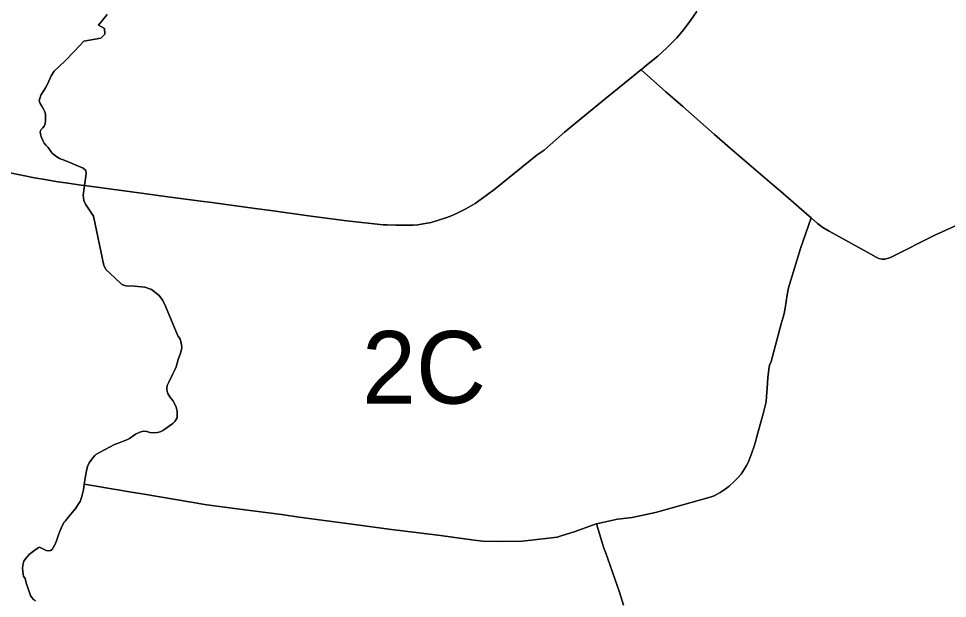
# Model space of a CAD drawing. Extents: x 152750 to 166250, y 378996 to 390000.
# Drawn here: x 161080 to 163640, y 380593 to 382190 of the extents above; entities that cross this region are included whole.
import ezdxf

# ---------------------------------------------------------------- set-up
doc = ezdxf.new("R2010")
doc.units = 0
doc.layers.add('BLT_Nummers', color=7, linetype='Continuous')
doc.layers.add('BLT_Shapes', color=7, linetype='Continuous')

msp = doc.modelspace()

# ---------------------------------------------------------------- linework, layer by layer
at = {"layer": 'BLT_Shapes'}
for p, q in [((162948.6, 382208.9), (162932.1, 382185.3)), ((161317.7, 382147.2), (161316.6, 382163.2)), ((162867.7, 382110.5), (162842, 382086.8)), ((161169.4, 382032.3), (161178.2, 382046)), ((162795.6, 382049.3), (162769.4, 382028.2)), ((162795.9, 382049.5), (162795.6, 382049.3)), ((162821.5, 382026.5), (162795.9, 382049.5)), ((162769.4, 382028.2), (162696.8, 381969.3)), ((162696.8, 381969.3), (162584.7, 381877.3)), ((162998.3, 381870.8), (162910.7, 381948.5)), ((161153, 381900.9), (161154.5, 381909.8)), ((161154.5, 381909.8), (161154.5, 381919.9)), ((161139.7, 381879.4), (161142.1, 381884.7)), ((161155.4, 381842.1), (161150.7, 381847.4)), ((162528.9, 381827.9), (162509.1, 381815.5)), ((161192.6, 381804.9), (161182.6, 381811.1)), ((161210.3, 381798.1), (161192.6, 381804.9)), ((162509.1, 381815.5), (162466.2, 381780.3)), ((162466.2, 381780.3), (162393.5, 381721.5)), ((161261.7, 381730.7), (161265.3, 381756.4)), ((161215.2, 381736.9), (161183, 381741.6)), ((161252.7, 381731.9), (161215.2, 381736.9)), ((161261.7, 381730.7), (161252.7, 381731.9)), ((161261.7, 381730.7), (161258, 381703.8)), ((161258, 381703.8), (161261.7, 381730.7)), ((161259.5, 381689.6), (161258, 381703.8)), ((162369.3, 381702.9), (162338.6, 381680.7)), ((162393.5, 381721.5), (162369.3, 381702.9)), ((162287.5, 381653.3), (162270.7, 381645.9)), ((161315, 381510.2), (161286.7, 381645.9)), ((161984.3, 381633.4), (161879, 381647.3)), ((162084.9, 381622.5), (161984.3, 381633.4)), ((162180.6, 381622.2), (162167.3, 381621.3)), ((163264.5, 381641.7), (163235.2, 381556.6)), ((163282.2, 381626), (163264.5, 381641.7)), ((163296.9, 381615.3), (163282.2, 381626)), ((162144, 381621), (162119.4, 381621.3)), ((162167.3, 381621.3), (162144, 381621)), ((163314.5, 381604.6), (163296.9, 381615.3)), ((163428.9, 381541), (163314.5, 381604.6)), ((163443.8, 381532.9), (163428.9, 381541)), ((161375.6, 381453.7), (161364.1, 381458.1)), ((161446.7, 381443.8), (161427.8, 381450.5)), ((161530.1, 381284.3), (161529.4, 381291.4)), ((161529.4, 381278.4), (161530.1, 381284.3)), ((163154.6, 381245.8), (163150.1, 381235.7)), ((161488.2, 381170.5), (161489.5, 381179.3)), ((163143.3, 381172.2), (163141.7, 381149)), ((163141.7, 381149), (163140.6, 381135)), ((161516.8, 381090.6), (161517.2, 381100)), ((161517.2, 381100), (161517, 381109)), ((163132, 381101.9), (163124.1, 381072.5)), ((161477.1, 381055.2), (161483.3, 381058.9)), ((161462.9, 381049.8), (161470.3, 381051.5)), ((161470.3, 381051.5), (161477.1, 381055.2)), ((161302.9, 380995.2), (161344.1, 381016.8)), ((161281.5, 380976.7), (161289.8, 380986.4)), ((163097.8, 380983.8), (163090.7, 380967.8)), ((161274.4, 380966.2), (161281.5, 380976.7)), ((161264.1, 380929.8), (161267.3, 380944.6)), ((163071.7, 380934.8), (163062.8, 380925.1)), ((163081, 380950), (163071.7, 380934.8)), ((161260.9, 380907.7), (161264.1, 380929.8)), ((161288.4, 380903.1), (161260.9, 380907.7)), ((163052.7, 380914.6), (163039, 380902.1)), ((163062.8, 380925.1), (163052.7, 380914.6)), ((161391.3, 380885.7), (161288.4, 380903.1)), ((162997.1, 380875.8), (162986.4, 380871.5)), ((161224, 380825), (161237.7, 380841.2)), ((161209.6, 380806.6), (161214.7, 380813.7)), ((161214.7, 380813.7), (161219.2, 380819.9)), ((161219.2, 380819.9), (161224, 380825)), ((162614.2, 380777.5), (162575.3, 380765.7)), ((162361, 380750.9), (162335.4, 380753.2)), ((162575.3, 380765.7), (162564.2, 380762)), ((161124.6, 380725.7), (161134.3, 380732)), ((161134.3, 380732), (161137.7, 380733.7)), ((161137.7, 380733.7), (161141.4, 380732.5)), ((161150.4, 380727.4), (161156.1, 380724.6)), ((161172.3, 380728), (161176.4, 380734)), ((161094.6, 380695.1), (161098.8, 380701.9)), ((161091.7, 380684.3), (161094.6, 380695.1)), ((161093.7, 380654.5), (161092.3, 380659.9))]:
    msp.add_line(p, q, dxfattribs=at)
for points in [[(162795.9, 382049.5), (162811, 382061.7), (162842, 382086.8), (162867.7, 382110.5), (162880.1, 382122.6), (162894.3, 382137.7), (162909.4, 382154.5), (162922.3, 382171.7), (162932.1, 382185.3), (162948.6, 382208.9), (162991.2, 382295.2), (162998.6, 382316.2), (163004.8, 382336.6), (163009.8, 382354.3), (163014.5, 382375.9), (163020.1, 382402.5), (163024, 382422.3), (163031.8, 382464.6), (163041, 382487.9), (163045.7, 382514.5), (163048.3, 382529.9), (163073.2, 382642.2), (163081.1, 382679), (163124.9, 382876.6)], [(161323.9, 382201.5), (161300.4, 382172.7), (161316.6, 382163.2), (161317.7, 382147.2), (161306.6, 382136.3), (161259.7, 382128.1), (161234.4, 382100.9), (161207.2, 382073.2), (161178.2, 382046), (161169.4, 382032.3), (161160.5, 382011.3), (161154.3, 382000), (161149.6, 381992.3), (161141.1, 381979.3), (161138.1, 381970.7), (161136.9, 381963.9), (161139.3, 381956.5), (161143.7, 381948.8), (161148.1, 381941.1), (161152.3, 381933.7), (161154.3, 381927), (161154.5, 381919.9), (161154.5, 381909.8), (161153, 381900.9), (161150.4, 381893.8), (161146.8, 381889.4), (161142.1, 381884.7), (161139.7, 381879.4), (161140, 381872.3), (161143, 381862.8), (161146.5, 381854.2), (161150.7, 381847.4), (161155.4, 381842.1), (161161.6, 381835.6), (161166.6, 381827.3), (161172.2, 381820), (161182.6, 381811.1), (161192.6, 381804.9), (161210.3, 381798.1), (161258.2, 381778), (161265, 381772.1), (161266.5, 381764.1), (161265.3, 381756.4), (161261.7, 381730.7)], [(161316.6, 382163.2), (161300.4, 382172.7), (161323.9, 382201.5)], [(162932.1, 382185.3), (162922.3, 382171.7), (162909.4, 382154.5)], [(161234.4, 382100.9), (161259.7, 382128.1), (161306.6, 382136.3), (161317.7, 382147.2)], [(162909.4, 382154.5), (162894.3, 382137.7), (162880.1, 382122.6), (162867.7, 382110.5)], [(163264.5, 381641.7), (163282.2, 381626), (163296.9, 381615.3), (163314.5, 381604.6), (163428.9, 381541), (163443.8, 381532.9), (163451.5, 381529.6), (163459.2, 381527.8), (163468.4, 381527.4), (163483.1, 381532.5), (163607.3, 381594.2), (163711.5, 381641.4), (163786.2, 381641.2), (163866.1, 381613.5), (163942.4, 381560.3), (164207.4, 381747.9), (164179.4, 381777.8), (164224.1, 381842.1), (164141.8, 381898.3), (164247.7, 381997), (164254.9, 381991.3), (164361.7, 382090.3), (164350.9, 382154.3)], [(161178.2, 382046), (161207.2, 382073.2), (161234.4, 382100.9)], [(162842, 382086.8), (162811, 382061.7), (162795.9, 382049.5)], [(161149.6, 381992.3), (161154.3, 382000), (161160.5, 382011.3), (161169.4, 382032.3)], [(161261.7, 381730.7), (161357.3, 381717.7), (161425.5, 381708.2), (161491.4, 381699.7), (161582.7, 381687.8), (161612.4, 381683.8), (161732.4, 381667.3), (161775.3, 381661.5), (161879, 381647.3), (161984.3, 381633.4), (162084.9, 381622.5), (162095.5, 381622.2), (162119.4, 381621.3), (162144, 381621), (162167.3, 381621.3), (162180.6, 381622.2), (162195.6, 381624.9), (162217.2, 381629), (162234.9, 381633.8), (162257.4, 381641.1), (162270.7, 381645.9), (162287.5, 381653.3), (162312.9, 381666.6), (162338.6, 381680.7), (162369.3, 381702.9), (162393.5, 381721.5), (162466.2, 381780.3), (162509.1, 381815.5), (162528.9, 381827.9), (162545.7, 381842.4), (162584.7, 381877.3), (162696.8, 381969.3), (162769.4, 382028.2), (162795.6, 382049.3), (162795.9, 382049.5)], [(162795.9, 382049.5), (162821.5, 382026.5), (162864.3, 381989), (162910.7, 381948.5), (162998.3, 381870.8), (163041.7, 381833.5), (163157.3, 381734.3), (163179.8, 381715), (163238.2, 381664.3), (163259.7, 381645.9), (163264.5, 381641.7)], [(162910.7, 381948.5), (162864.3, 381989), (162821.5, 382026.5)], [(161138.1, 381970.7), (161141.1, 381979.3), (161149.6, 381992.3)], [(161139.3, 381956.5), (161136.9, 381963.9), (161138.1, 381970.7)], [(161152.3, 381933.7), (161148.1, 381941.1), (161143.7, 381948.8), (161139.3, 381956.5)], [(161154.5, 381919.9), (161154.3, 381927), (161152.3, 381933.7)], [(161150.7, 381847.4), (161146.5, 381854.2), (161143, 381862.8), (161140, 381872.3), (161139.7, 381879.4)], [(161142.1, 381884.7), (161146.8, 381889.4), (161150.4, 381893.8), (161153, 381900.9)], [(162584.7, 381877.3), (162545.7, 381842.4), (162528.9, 381827.9)], [(163157.3, 381734.3), (163041.7, 381833.5), (162998.3, 381870.8)], [(161166.6, 381827.3), (161161.6, 381835.6), (161155.4, 381842.1)], [(161182.6, 381811.1), (161172.2, 381820), (161166.6, 381827.3)], [(160920.5, 381800.8), (160932.2, 381797.2), (160959.8, 381789.2), (160985.8, 381782.4), (161019.2, 381774.2), (161041.4, 381768.8), (161069.7, 381762.6), (161092.3, 381757.9), (161123.3, 381751.7), (161157.6, 381746.1), (161183, 381741.6), (161215.2, 381736.9), (161252.7, 381731.9), (161261.7, 381730.7)], [(161265.3, 381756.4), (161266.5, 381764.1), (161265, 381772.1), (161258.2, 381778), (161210.3, 381798.1)], [(161092.3, 381757.9), (161069.7, 381762.6), (161041.4, 381768.8), (161019.2, 381774.2)], [(161183, 381741.6), (161157.6, 381746.1), (161123.3, 381751.7), (161092.3, 381757.9)], [(161491.4, 381699.7), (161425.5, 381708.2), (161357.3, 381717.7), (161261.7, 381730.7)], [(163238.2, 381664.3), (163179.8, 381715), (163157.3, 381734.3)], [(161258, 381703.8), (161259.5, 381689.6), (161263.9, 381678.7), (161275.2, 381662.7), (161286.7, 381645.9), (161315, 381510.2), (161320.9, 381498.1), (161344.4, 381477.2), (161364.1, 381458.1), (161375.6, 381453.7), (161399.6, 381453.4), (161427.8, 381450.5), (161446.7, 381443.8), (161467.7, 381427.6), (161477.8, 381413.9), (161484.6, 381398.2), (161519.3, 381316.6), (161522.2, 381311.4), (161525.6, 381306.9), (161527.4, 381300.4), (161529.4, 381291.4), (161530.1, 381284.3), (161529.4, 381278.4), (161526.5, 381269), (161520.2, 381251.1), (161513.9, 381230.9), (161510.1, 381220.5), (161505.4, 381211.8), (161494.7, 381190.7), (161489.5, 381179.3), (161488.2, 381170.5), (161489.1, 381163.3), (161491.5, 381157.9), (161494, 381152.8), (161499.1, 381146), (161505.4, 381138.4), (161509.2, 381131.5), (161513.9, 381119.8), (161517, 381109), (161517.2, 381100), (161516.8, 381090.6), (161510.9, 381080.5), (161505.3, 381075.1), (161496.1, 381068.5), (161483.3, 381058.9), (161477.1, 381055.2), (161470.3, 381051.5), (161462.9, 381049.8), (161451.5, 381048.9), (161441.6, 381050.3), (161433, 381052.9), (161424.2, 381053.8), (161413.7, 381050.6), (161402.1, 381045.2), (161396.1, 381041), (161385.6, 381033.9), (161377.9, 381029.6), (161370.8, 381026.7), (161357.1, 381021.3), (161344.1, 381016.8), (161302.9, 380995.2), (161293.2, 380989.2), (161289.8, 380986.4), (161281.5, 380976.7), (161274.4, 380966.2), (161270.2, 380956.8), (161267.3, 380944.6), (161264.1, 380929.8), (161260.9, 380907.7)], [(161879, 381647.3), (161775.3, 381661.5), (161732.4, 381667.3), (161612.4, 381683.8), (161582.7, 381687.8), (161491.4, 381699.7)], [(161286.7, 381645.9), (161275.2, 381662.7), (161263.9, 381678.7), (161259.5, 381689.6)], [(162338.6, 381680.7), (162312.9, 381666.6), (162287.5, 381653.3)], [(163264.5, 381641.7), (163259.7, 381645.9), (163238.2, 381664.3)], [(162119.4, 381621.3), (162095.5, 381622.2), (162084.9, 381622.5)], [(162270.7, 381645.9), (162257.4, 381641.1), (162234.9, 381633.8), (162217.2, 381629), (162195.6, 381624.9), (162180.6, 381622.2)], [(163154.6, 381245.8), (163182.4, 381349.6), (163187.5, 381367.6), (163190.2, 381377.9), (163192.7, 381392.9), (163199, 381429.3), (163202.4, 381448.3), (163235.2, 381556.6), (163264.5, 381641.7)], [(163711.5, 381641.4), (163607.3, 381594.2), (163483.1, 381532.5)], [(163235.2, 381556.6), (163202.4, 381448.3), (163199, 381429.3), (163192.7, 381392.9), (163190.2, 381377.9)], [(163459.2, 381527.8), (163451.5, 381529.6), (163443.8, 381532.9)], [(163483.1, 381532.5), (163468.4, 381527.4), (163459.2, 381527.8)], [(161364.1, 381458.1), (161344.4, 381477.2), (161320.9, 381498.1), (161315, 381510.2)], [(161427.8, 381450.5), (161399.6, 381453.4), (161375.6, 381453.7)], [(161477.8, 381413.9), (161467.7, 381427.6), (161446.7, 381443.8)], [(161529.4, 381291.4), (161527.4, 381300.4), (161525.6, 381306.9), (161522.2, 381311.4), (161519.3, 381316.6), (161484.6, 381398.2), (161477.8, 381413.9)], [(163190.2, 381377.9), (163187.5, 381367.6), (163182.4, 381349.6), (163154.6, 381245.8)], [(161520.2, 381251.1), (161526.5, 381269), (161529.4, 381278.4)], [(161510.1, 381220.5), (161513.9, 381230.9), (161520.2, 381251.1)], [(162672.9, 380798.7), (162731, 380811.1), (162771.4, 380815.5), (162835.7, 380829.9), (162851.8, 380833.9), (162986.4, 380871.5), (162997.1, 380875.8), (163014.3, 380884.3), (163028.1, 380894.2), (163039, 380902.1), (163052.7, 380914.6), (163062.8, 380925.1), (163071.7, 380934.8), (163081, 380950), (163086.5, 380959.5), (163090.7, 380967.8), (163097.8, 380983.8), (163107.1, 381009.3), (163111.3, 381024), (163113.8, 381035.3), (163124.1, 381072.5), (163132, 381101.9), (163138.4, 381123.5), (163140.6, 381135), (163141.7, 381149), (163143.3, 381172.2), (163145.5, 381200.8), (163148.3, 381223.6), (163150.1, 381235.7), (163154.6, 381245.8)], [(161489.5, 381179.3), (161494.7, 381190.7), (161505.4, 381211.8), (161510.1, 381220.5)], [(163150.1, 381235.7), (163148.3, 381223.6), (163145.5, 381200.8), (163143.3, 381172.2)], [(161509.2, 381131.5), (161505.4, 381138.4), (161499.1, 381146), (161494, 381152.8), (161491.5, 381157.9), (161489.1, 381163.3), (161488.2, 381170.5)], [(161517, 381109), (161513.9, 381119.8), (161509.2, 381131.5)], [(163140.6, 381135), (163138.4, 381123.5), (163132, 381101.9)], [(161505.3, 381075.1), (161510.9, 381080.5), (161516.8, 381090.6)], [(161483.3, 381058.9), (161496.1, 381068.5), (161505.3, 381075.1)], [(163124.1, 381072.5), (163113.8, 381035.3), (163111.3, 381024), (163107.1, 381009.3), (163097.8, 380983.8)], [(161344.1, 381016.8), (161357.1, 381021.3), (161370.8, 381026.7), (161377.9, 381029.6), (161385.6, 381033.9)], [(161385.6, 381033.9), (161396.1, 381041), (161402.1, 381045.2), (161413.7, 381050.6)], [(161413.7, 381050.6), (161424.2, 381053.8), (161433, 381052.9), (161441.6, 381050.3)], [(161441.6, 381050.3), (161451.5, 381048.9), (161462.9, 381049.8)], [(161289.8, 380986.4), (161293.2, 380989.2), (161302.9, 380995.2)], [(161267.3, 380944.6), (161270.2, 380956.8), (161274.4, 380966.2)], [(163090.7, 380967.8), (163086.5, 380959.5), (163081, 380950)], [(161260.9, 380907.7), (161258.7, 380892.2), (161255.2, 380877.5), (161252.7, 380868.2), (161249.6, 380859.7), (161245.3, 380853.4), (161237.7, 380841.2), (161224, 380825), (161219.2, 380819.9), (161214.7, 380813.7), (161209.6, 380806.6), (161205.6, 380802.9), (161200.5, 380795), (161194, 380778.5), (161189.2, 380765.5), (161184.3, 380751.8), (161180.4, 380742.2), (161176.4, 380734), (161172.3, 380728), (161168.3, 380725.4), (161162.4, 380724), (161156.1, 380724.6), (161150.4, 380727.4), (161145.1, 380730.3), (161141.4, 380732.5), (161137.7, 380733.7), (161134.3, 380732), (161124.6, 380725.7), (161110.2, 380714.4), (161103.4, 380707.9), (161098.8, 380701.9), (161094.6, 380695.1), (161091.7, 380684.3), (161090.6, 380675.8), (161091.2, 380667.6), (161092.3, 380659.9), (161093.7, 380654.5), (161098, 380647.4), (161100.8, 380635.8), (161106.2, 380619.6), (161109.9, 380608.8), (161113, 380600.6), (161116.4, 380595.2), (161121.2, 380589.8)], [(161255.2, 380877.5), (161258.7, 380892.2), (161260.9, 380907.7)], [(161260.9, 380907.7), (161288.4, 380903.1), (161391.3, 380885.7), (161420.3, 380880.7), (161598.9, 380850.9), (161682.3, 380839.4), (161804.2, 380823.7), (161853.5, 380817), (162005.6, 380796.2), (162100.1, 380783.3), (162243, 380766.3), (162335.4, 380753.2), (162361, 380750.9), (162400.8, 380749.8), (162467.9, 380750.6), (162541.8, 380758.6), (162564.2, 380762), (162575.3, 380765.7), (162614.2, 380777.5), (162672, 380798.5), (162672.9, 380798.7)], [(161598.9, 380850.9), (161420.3, 380880.7), (161391.3, 380885.7)], [(163039, 380902.1), (163028.1, 380894.2), (163014.3, 380884.3), (162997.1, 380875.8)], [(161237.7, 380841.2), (161245.3, 380853.4), (161249.6, 380859.7)], [(161249.6, 380859.7), (161252.7, 380868.2), (161255.2, 380877.5)], [(162986.4, 380871.5), (162851.8, 380833.9), (162835.7, 380829.9), (162771.4, 380815.5)], [(161804.2, 380823.7), (161682.3, 380839.4), (161598.9, 380850.9)], [(161176.4, 380734), (161180.4, 380742.2), (161184.3, 380751.8), (161189.2, 380765.5), (161194, 380778.5), (161200.5, 380795), (161205.6, 380802.9), (161209.6, 380806.6)], [(162335.4, 380753.2), (162243, 380766.3), (162100.1, 380783.3), (162005.6, 380796.2), (161853.5, 380817), (161804.2, 380823.7)], [(162771.4, 380815.5), (162731, 380811.1), (162672.9, 380798.7)], [(162672.9, 380798.7), (162672, 380798.5), (162614.2, 380777.5)], [(162747.6, 380574.5), (162736.7, 380610.5), (162697.6, 380720.1), (162693.5, 380731.2), (162672.9, 380798.7)], [(162672.9, 380798.7), (162693.5, 380731.2), (162697.6, 380720.1), (162736.7, 380610.5), (162747.6, 380574.5)], [(162564.2, 380762), (162541.8, 380758.6), (162467.9, 380750.6), (162400.8, 380749.8), (162361, 380750.9)], [(161141.4, 380732.5), (161145.1, 380730.3), (161150.4, 380727.4)], [(161156.1, 380724.6), (161162.4, 380724), (161168.3, 380725.4), (161172.3, 380728)], [(161098.8, 380701.9), (161103.4, 380707.9), (161110.2, 380714.4), (161124.6, 380725.7)], [(161092.3, 380659.9), (161091.2, 380667.6), (161090.6, 380675.8), (161091.7, 380684.3)], [(161100.8, 380635.8), (161098, 380647.4), (161093.7, 380654.5)], [(161113, 380600.6), (161109.9, 380608.8), (161106.2, 380619.6), (161100.8, 380635.8)], [(161126.9, 380585.3), (161121.2, 380589.8), (161116.4, 380595.2), (161113, 380600.6)]]:
    msp.add_lwpolyline(points, dxfattribs=at)

# ---------------------------------------------------------------- texts
at = {"layer": 'BLT_Nummers'}
msp.add_text('2C', height=200, dxfattribs=at).set_placement((162026.6, 381129.6))

doc.saveas('drawing.dxf')
